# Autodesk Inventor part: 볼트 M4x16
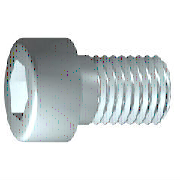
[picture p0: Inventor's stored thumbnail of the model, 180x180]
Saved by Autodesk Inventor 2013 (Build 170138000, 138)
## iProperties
Created: 2012-02
Part Number: 볼트 M4x16
Material: 스테인리스강
Description: 6각 소켓 머리 캡 나사
Document SubType Name: Modeling
Standard: ISO 4762
Designer: mduedu
Standard Revision: Fourth edition 2004-03-01
Standards Organization: ISO
Language: ko-KR
Size Designation: M4 x 16
Categories: <MemberInstance><Categories><Category DisplayName="조임쇠" InternalName="e4da775c-781d-43d5-af7c-5136215cf5a6" Mnemonic="FSTN"><Category DisplayName="볼트" InternalN
Density: 7.75 g/cm^3
IsCustomPart: 0
Author: mduedu
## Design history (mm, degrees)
sketch "스케치1"
  geometry: L1 (-1, 0)-(16, 0); L2 (16, 0)-(16, 2); L3 (16, 2)-(1.75, 2); L4 (1.75, 2)-(1.32, 2); L5 (1.32, 2)-(0, 2); L6 (0, 2)-(0, 3.5); L7 (0, 3.5)-(-4, 3.5); L8 (-4, 3.5)-(-4, 1.732); L9 (-4, 1.732)-(-2, 1.732); L10 (-2, 1.732)-(-1, 0); L11 (-8, 0)-(20, 0) reference; L12 (0, -0.7)-(0, 4.2) reference; L13 (1.75, 2)-(0, 2)
  constraints: 22 end point, 6 parallel, 2 collinear, 2 perpendicular, 1 horizontal, 1 point on line
  dimensions: "d1" = 14.25 distance from line of L3.end L2 (= GEL); "d2" = 0.42952 distance of L4.end L3.end (computed from GAL); "d3" = 4 distance between parallel lines of L8 L6 (= KOH); "d4" = 2 distance of L8.end L9.end (= INTI); "d5" = 60 deg angle of L10 L1; "d6" = 4 diameter of L3 L1 (= GD); "d7" = 4 diameter of L5 L1 (= BDM); "d8" = 3.4641 diameter of L9 L1 (= 1.1547 x SW); "d9" = 7 diameter of L7 L1 (= KOD); "d26" = 16 distance between parallel lines of L12 L2 (= NLG)
revolve "본체" sketch "스케치1" stored, may be unused: angle "d10" = 90 deg
sketch "스케치2"
  geometry: L1 (0, -4.9)-(0, 4.9) reference; L2 (-4.9, 0)-(4.9, 0) reference; L3 (1.732, 0)-(0.866, -1.5); L4 (0.866, -1.5)-(-0.866, -1.5); L5 (-0.866, -1.5)-(-1.732, 0); L6 (-1.732, 0)-(-0.866, 1.5); L7 (-0.866, 1.5)-(0.866, 1.5); L8 (0.866, 1.5)-(1.732, 0); 2 further points
  constraints: 12 end point, 1 coincident, 1 horizontal alignment, 1 point on line, 12 other
extrude "슬롯" join sketch "스케치2" stored distance "d11" = 10; taper "d12" = 0 deg
workplane "Work Plane1"
fillet "Fillet2" dims "d30" = 0.1 (= R)
body "Solid1"
fillet "모깎기1" dims "d17" = 0.4 (= RR)
feature "스레드" dims "d13" = 14.25 (= GEL), "d14" = 0
chamfer "모따기1" distance "d15" = 0.42941 (= -0.5 x SPD + 0.5 x GD); stored, may be unused: second distance "d16" = 0.42941 (= GUL), angle "d27" = 45 deg
other parameters: "GD" = 4 [user parameter; used in 2 equation terms], "NLG" = 16 [user parameter; used in 1 equation term], "GEL" = 14.25 [user parameter; used in 2 equation terms], "KOD" = 7 [user parameter; used in 1 equation term], "KOH" = 4 [user parameter; used in 1 equation term], "INTI" = 2 [user parameter; used in 1 equation term], "GAL" = 0.42941 (= 0.61345 x PTC) [user parameter; used in 1 equation term], "GUL" = 0.42941 (= 0.61345 x PTC) [user parameter; used in 1 equation term], "BDM" = 4 (= NND) [user parameter; used in 1 equation term], "SW" = 3 [user parameter; used in 2 equation terms], "RR" = 0.4 [user parameter; used in 1 equation term], "SPD" = 3.14117 (= NND - 1.2269 x PTC) [user parameter; used in 1 equation term], "d19" = 0, "d28" = 0, "d29" = 0, "R" = 0.1 [user parameter; used in 1 equation term], "TOA" = 30 deg [user parameter], "GD1" = 3.14117 (= THREADDIA - 1.2269 x PTC) [user parameter], "THREADDIA" = 4 [user parameter; used in 1 equation term], "FAWI" = 45 deg [user parameter], "TPU" = 14.28571 (computed from PTC) [user parameter], "PTC" = 0.7 [user parameter; used in 5 equation terms], "NND" = 4 [user parameter; used in 2 equation terms], "E0" = 3.465 (= 1.155 x SW) [user parameter]
